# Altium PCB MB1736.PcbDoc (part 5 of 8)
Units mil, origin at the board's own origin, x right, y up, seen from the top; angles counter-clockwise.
Board outline 5905.51 x 3779.53 mil, 6 copper layers (Top Layer, L2_GND, L3_SIG, L4_VCC, L5_GND, Bottom Layer), stack 117.811 mil thick; 481 components, 387 nets, 1904 pads, 1200 vias.
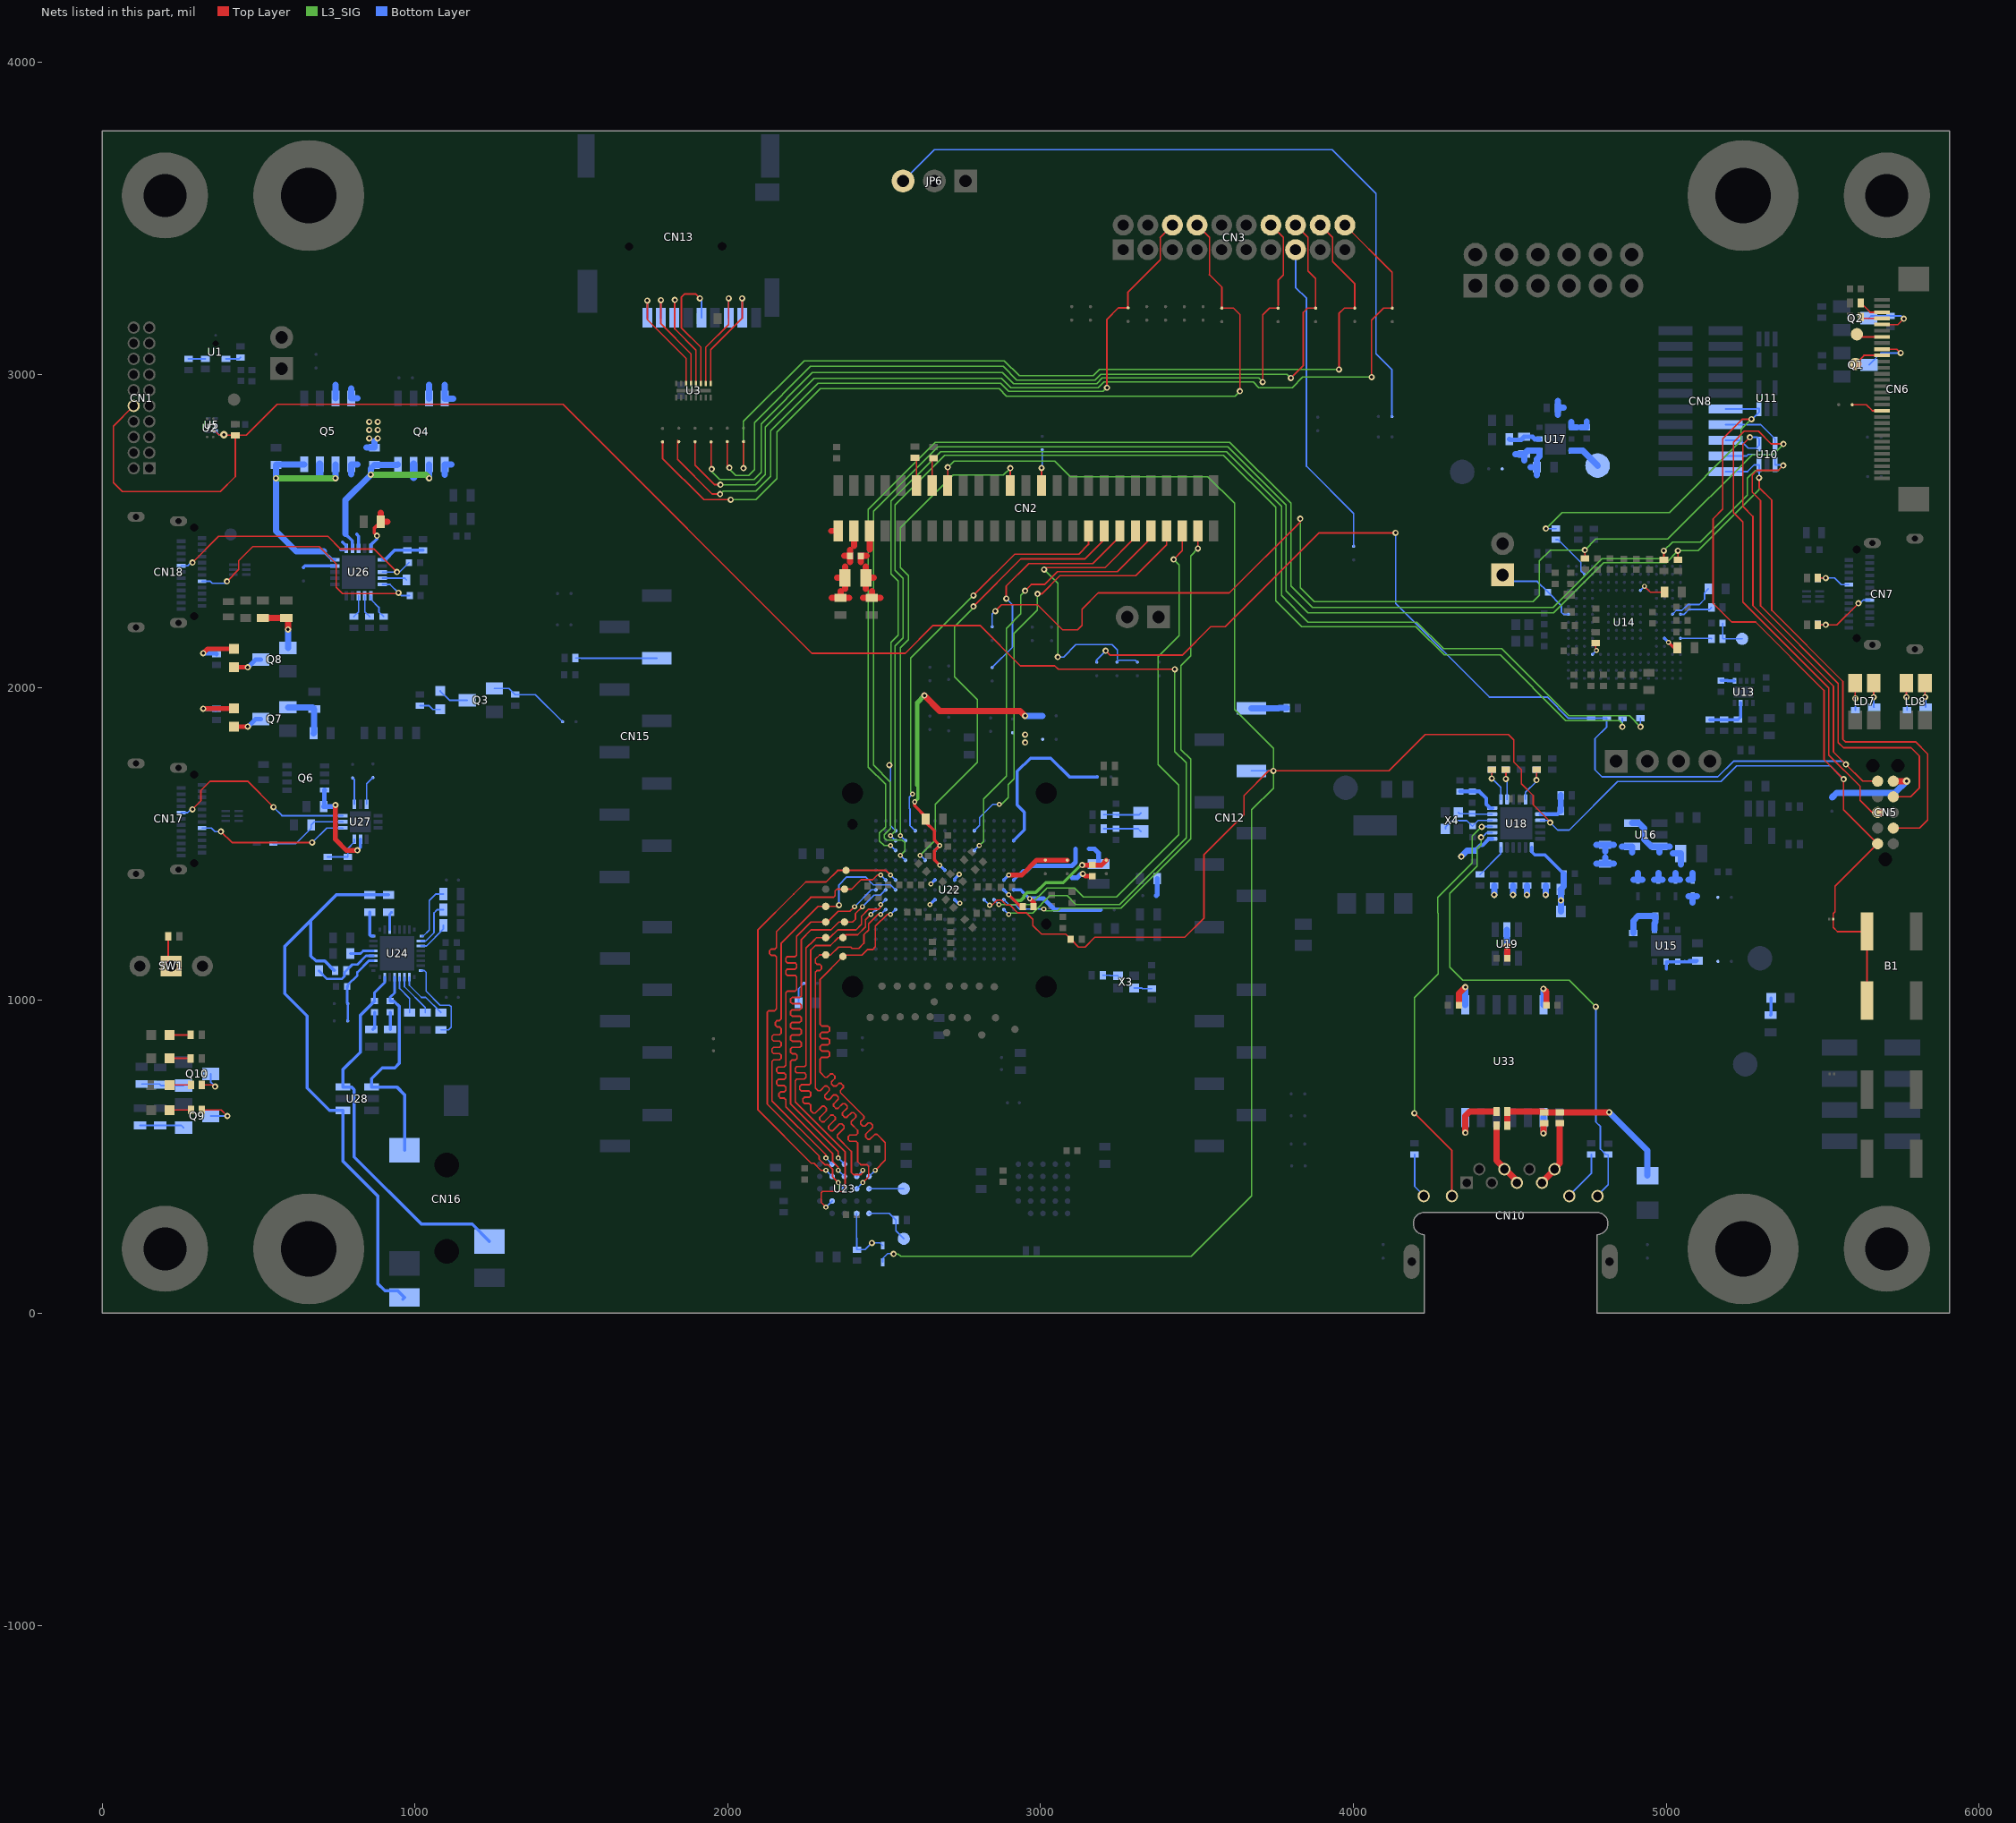
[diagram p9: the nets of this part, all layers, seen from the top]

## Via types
v1: diameter 20, hole 10, Top Layer to Bottom Layer, tented both sides, 518 vias
v2: diameter 16, hole 8, Top Layer to Bottom Layer, tented both sides, 311 vias
v3: diameter 24, hole 10, Top Layer to Bottom Layer, tented both sides, 301 vias
v4: diameter 24, hole 12, Top Layer to Bottom Layer, tented both sides, 61 vias
v5: diameter 23.62, hole 11.81, Top Layer to Bottom Layer, 9 vias

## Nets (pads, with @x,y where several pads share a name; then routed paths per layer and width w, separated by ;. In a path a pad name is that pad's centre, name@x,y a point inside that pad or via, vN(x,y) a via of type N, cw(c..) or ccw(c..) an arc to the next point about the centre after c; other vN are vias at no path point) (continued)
LCD_R0: CN2.3 U22.J2 | length 1725.9
  Top Layer w5: v1(3502.87,2445) 3502.87,2470 CN2.3@3502.88,2501.22
  L3_SIG w4: v2(3010,1292.5) 3015.5,1287 3055.02,1287 3063.02,1295 3257,1295 3479.5,1517.5 3479.5,1771.5 3449,1802 3449,2071 3479.5,2101.5 3479.5,2421.62 v1(3502.87,2445)
  Bottom Layer w5: U22.J2@2882.38,1322.25 2889.8,1314.83 2899.61,1305 2919.99,1305 2932.49,1292.5 v2(3010,1292.5)
LCD_R1: CN2.5 U22.J3 | length 1757.8
  Top Layer w5: v1(3425,2410) 3452.87,2437.86 3452.87,2467 CN2.5@3452.88,2501.22
  L3_SIG w4: v2(2866.61,1306.5) 2867.11,1306 2966.44,1306 3017.44,1357 3018.04,1357 3020.04,1359 3108.01,1359 3136,1331 3242,1331 3441,1530 3441,1688.99 3376,1753.99 3376,2099 3443,2166 3443,2392 v1(3425,2410)
  Bottom Layer w4: U22.J3@2850.87,1322.24 v2(2866.61,1306.5)
LCD_R2: CN2.7 U22.B5 | length 1379.6
  Top Layer w5: v1(2990,2300) 3003.47,2300 3061.48,2358 3304,2358 3402.87,2456.87 3402.87,2471 CN2.7@3402.88,2501.22
  L3_SIG w4: v2(2867.61,1627) 2875.02,1627 2896,1647.98 2896,1689.95 2915,1708.95 2915,2173 2990,2248 v1(2990,2300)
  Bottom Layer w5: U22.B5@2787.9,1542.73 2805,1559.84 2805,1585 2847,1627 v2(2867.61,1627)
LCD_R3: CN2.9 U22.D5 | length 1393.1
  Top Layer w5: v1(2950,2310) 2970,2330 3012.25,2330 3053.26,2371 3245.88,2371 3352.88,2478 CN2.9@3352.88,2501.22
  L3_SIG w4: v2(2803.62,1495.45) 2817,1508.84 2817,1644.92 2890,1717.92 2890,2190 2936.75,2236.75 2936.75,2295.8 v1@2945.95,2305 ; v1@2946,2305 2950,2309 v1(2950,2310)
  Bottom Layer w4: U22.D5@2787.9,1479.74 v2(2803.62,1495.45)
LCD_R4: CN2.11 SB47.1 SB68.1 | length 969.2
  Top Layer w5: v1(3011,2378) 3017,2384 3205.88,2384 3302.88,2481 CN2.11@3302.88,2501.22
  L3_SIG w4: v1(3011,2378) 3055,2334 v1(3055,2098)
  Bottom Layer w4: v1(3055,2098) 3073,2098 3113,2138 3228,2138 3246,2120 3246,2089
  Bottom Layer w5: SB68.1@3244.16,2081.62 3250.48,2087.94 3302.84,2087.94 SB47.1@3309.16,2081.62
LCD_R5: CN2.13 SB53.1 | length 742.1
  Top Layer w5: v1(2890,2285) 2890,2325 2962.01,2397 3167.01,2397 3252.88,2482.88 CN2.13@3252.88,2501.22
  Bottom Layer w5: SB53.1@2845,2064.68 2910,2129.67 2910,2265 v1(2890,2285)
LCD_R6: CN2.15 U22.E10 | length 1483.7
  Top Layer w5: v1(2785,2260) 2937.01,2412 3142.01,2412 3202.87,2472.86 3202.87,2485 CN2.15@3202.88,2501.22
  L3_SIG w4: v2(2614.66,1463.97) 2663.14,1512.44 2663.14,1612.43 2663.76,1613.06 2663.76,1626.76 2798,1761 2798,1962 2725,2035 2725,2195 2785,2255 v1(2785,2260)
  Bottom Layer w4: v2(2614.66,1463.97) 2623.81,1454.82 U22.E10@2630.42,1448.24
LCD_R7: CN2.17 U22.B11 | length 1328
  Top Layer w5: v1(2785,2295) 2917.01,2427 3122.01,2427 3152.87,2457.85 3152.87,2486 CN2.17@3152.88,2501.22
  L3_SIG w4: v2(2590,1660) 2584.87,1665.12 2584.87,2094.86 v1(2785,2295)
  Bottom Layer w5: v2(2590,1660) 2580,1650 2580,1614.53 2582.41,1612.12 2582.41,1559.2 2586.31,1555.31 U22.B11@2598.93,1542.73
LCD_VSYNC: CN2.28 U22.C12 | length 1513.9
  Top Layer w5: CN2.28@2902.88,2646.31 v1(2902.87,2702.12)
  L3_SIG w4: v2(2551.67,1526.95) 2551.67,2127.67 2577,2153 2577,2358.67 2551.67,2384 2551.67,2511.67 2720,2680 2880.74,2680 v1(2902.87,2702.12)
  Bottom Layer w4: v2(2551.67,1526.95) 2559.81,1518.82 U22.C12@2567.43,1511.24
MCU.JTDI: CN5.8 CN8.8 R49.2 SB72.1 U10.5 | length 5134.6
  Top Layer w5: v1(2855,2245) 2875,2265 2990,2265 3070,2185 3118,2185 3132,2199 3132,2251 3184,2303 3603.01,2303 3830,2530 v1(3830,2540) ; R49.2@4740,2412.72 v1(4740,2440) ; v1(5375,2779.36) 5335.63,2779.36 5295,2820 5250,2820 5215,2785 5215,2560 5245,2530 5245,2274 5520,1999 5520,1785 5620,1685 5620,1640 5658.78,1601.22 CN5.8@5676.3,1601.22
  L3_SIG w4: v1(3830,2540) 3830,2320 3875,2275 4575,2275 4595,2295 4595,2405 4630,2440 v1(4740,2440) 4775,2475 5005,2475 5275,2745 5340.63,2745 v1(5375,2779.36)
  Bottom Layer w5: SB72.1@2845,2194.67 2845,2235 v1(2855,2245) ; CN8.8@5190.13,2841 5302.46,2841 5348.35,2795.1 U10.5@5348.35,2779.36 v1(5375,2779.36)
MCU.MCO: C83.2 R78.2 TP4.1 | length 112.3
  Bottom Layer w5: C83.2@5180.59,2206.22 5180.59,2156.22 TP4.1@5242.87,2156.22
MCU.SWCLK: CN5.4 CN8.4 R73.2 U10.1 U22.D13 | length 6577.1
  Top Layer w5: R73.2@4992.76,2408.62 v1(4992.76,2437.75) ; v1(5374.4,2710.6) 5358.79,2695 5290,2695 5275,2680 5275,2625 5301.89,2598.1 5301.89,2261.89 5550,2013.77 5550,1825 5567,1808 5783,1808 5810,1781 5810,1680 5781.22,1651.22 CN5.4@5726.3,1651.22
  L3_SIG w4: v2(2520.17,1495.45) 2499.54,1495.45 2485,1510 2485,1535 2504.16,1554.16 2504.16,1691.23 2449,1746.39 2449,2570.59 2663.41,2785 3605,2785 3800,2590 3800,2325 3869,2256 4639.02,2256 4795.02,2412 4985.02,2412 4992.76,2419.74 v1(4992.76,2437.75) 5020,2465 5110,2465 5260,2615 5260,2670 5285,2695 5358.79,2695 v1(5374.4,2710.6)
  Bottom Layer w4: v2(2520.17,1495.45) 2528.81,1486.82 U22.D13@2535.94,1479.74
  Bottom Layer w5: CN8.4@5190.13,2741 5257.85,2741 5262.76,2745.91 5343.35,2745.91 5348.35,2740.91 U10.1@5348.35,2712.44 5372.57,2712.43 v1(5374.4,2710.6)
MCU.SWDIO: CN5.2 CN8.2 R74.2 U10.3 U22.E12 | length 6470
  Top Layer w5: R74.2@5037.76,2408.62 v1(5037.76,2437.75) ; v1(5297.17,2670.91) 5297.17,2640 5337.5,2599.67 5337.5,2247.5 5565,2020 5565,1835 5573,1827 5797,1827 5836,1788 5836,1577 5810.22,1551.22 CN5.2@5726.3,1551.22
  L3_SIG w4: v2(2551.67,1463.97) 2565.67,1477.97 2565.67,1505 2557.71,1512.95 2507.04,1512.95 2500,1520 2500,1530 2520.16,1550.16 2520.16,1697.85 2465,1753.01 2465,2563.95 2671.04,2770 3598.78,2770 3785,2583.77 3785,2310 3855,2240 4640,2240 4800,2400 5000,2400 v1(5037.76,2437.75) 5102.76,2437.75 5297.17,2632.17 v1(5297.17,2670.91)
  Bottom Layer w4: v2(2551.67,1463.97) 2561.32,1454.32 ; 2561.34,1454.32 U22.E12@2567.43,1448.24
  Bottom Layer w5: CN8.2@5190.13,2691 5260.35,2691 5281.79,2712.43 U10.3@5297.17,2712.44 v1(5297.17,2670.91)
MCU.SWO: CN5.6 CN8.6 R9.1 R51.2 SB31.1 U10.4 | length 4701.4
  Top Layer w5: v1(3208,2118) 3222,2104 3452.78,2104 3543.78,2195 3590.01,2195 3890.01,2495 v1(4135,2495) ; v1(5267.76,2800.91) 5245,2778.15 5245,2580 5277.5,2547.5 5277.5,2262.5 5535,2005 5535,1795 v1(5575,1755) 5628.78,1701.22 CN5.6@5676.3,1701.22
  Bottom Layer w5: SB31.1@3179.16,2081.62 3179.16,2089.16 v1(3208,2118) ; v1(4135,2495) 4135,2270 4435,1970 4620.01,1970 4687.73,1902.27 R51.2@4810,1902.28 4810,1875 4772.5,1837.5 4772.5,1737.5 4795,1715 5165,1715 5215,1765 5565,1765 v1(5575,1755) ; CN8.6@5190.13,2791 5237.68,2791 5262.77,2765.91 5287.75,2765.91 5297.17,2775.33 5297.17,2795.91 5292.17,2800.91 v1(5267.76,2800.91)
MCU.VCP_RX: R56.2 U22.C13 | length 4065.6
  L3_SIG w4: v2(2520.16,1526.97) 2534.16,1540.97 2534.16,2133.16 2560,2159 2560,2350.16 2534.16,2376 2534.16,2584.16 2693,2743 3585,2743 3751.5,2576.5 3751.5,2278.5 3835,2195 4200,2195 4290.66,2104.34 4469.33,2104.34 4678.67,1895 4850,1895 4860,1885 v1(4860,1875)
  Bottom Layer w4: v2(2520.16,1526.97) U22.C13@2535.89,1511.24
  Bottom Layer w5: v1(4860,1875) R56.2@4860,1902.28
MCU.VCP_TX: R52.2 U22.B13 | length 4104.7
  L3_SIG w4: v1(2516.27,1752.85) 2522,1758.59 2522,2145 2545,2168 2545,2341 2522,2364 2522,2597 2680,2755 3595,2755 3770,2580 3770,2295 3855,2210 4201.98,2210 4287.64,2124.34 4474.33,2124.34 4688.67,1910 4882.76,1910 v1(4917.76,1875)
  Bottom Layer w5: v1(2516.27,1752.85) 2516.27,1752.5 2520,1748.77 2520,1558.62 2527.81,1550.82 U22.B13@2535.94,1542.73 ; v1(4917.76,1875) R52.2@4917.76,1903.19
MIC: C137.2 C138.2 CN16.2 R132.1 U28.4 | length 1944.2
  Bottom Layer w10: 666.5,1254.06 666.5,1142.5 683,1126 711,1126 R132.1@741.21,1095.79 ; C137.2@915,1337.56 C138.2@855,1337.56 747.56,1337.56 583,1173 583,1022 655,950 655,720 726.17,648.83 U28.4@769.71,648.83 769.71,485.29 880,375 880,95 903.13,71.87 944.33,71.87 CN16.2@965.77,50.42 CN16.2@960.32,45
MIC_DET: CN1.10 R7.2 U2.6 U5.6 U22.K2 | length 5672.2
  Top Layer w5: CN1.10@100,2901.22 35,2836.22 35,2656 64,2627 377,2627 425,2675 R7.2@425,2807.28 ; U2.6@354.45,2821.02 360.12,2821.02 372.14,2809 v3(389,2809) 390.72,2807.28 407.28,2807.28 ; 407,2807 407.28,2807.28 ; v1(3429.01,2059) 3056,2059 3045,2070 2935,2070 2806,2199 2656,2199 2567,2110 2268.78,2110 1472.56,2906.22 559.22,2906.22 460.28,2807.28 R7.2@425,2807.28 ; 407.28,2807.28 R7.2@425,2807.28
  L3_SIG w4: v2(2898.11,1275) 2903.1,1280 2975,1280 3030,1335 3085.01,1335 3113,1307 3252,1307 3465,1520 3465,1760 3429.01,1796 v1(3429.01,2059)
  Bottom Layer w4: U22.K2@2882.37,1290.75 v2(2898.11,1275)
  Bottom Layer w5: U5.6@361.81,2820.32 373.13,2809 v3(389,2809)
NetC5_2: C5.2 Q6.4 U27.5 | length 327.2
  Top Layer w15: v1(745,1625) 745,1515 780,1480 v1(815,1480)
  Bottom Layer w10: v1(815,1480) 825,1490 825,1508 U27.5@825.02,1515.13
  Bottom Layer w15: Q6.4@710.04,1672.83 710.04,1622.48 C5.2@707.56,1620 740,1620 v1(745,1625)
NetC16_1: C16.1 C18.2 CN2.47 CN2.49 R17.2 | length 393.5
  Top Layer w20: 2330.29,2501.22 CN2.49@2352.88,2501.22 ; 2348.68,2351.22 C16.1@2374.42,2351.22 ; 2360,2308.18 R17.2@2360,2287.57 ; 2372.1,2421.22 C18.2@2390.18,2421.22 ; 2374.42,2315.64 C16.1@2374.42,2351.22 ; 2374.42,2386.8 C16.1@2374.42,2351.22 ; 2402.87,2452.99 2402.87,2477 CN2.47@2402.88,2501.22 ; R17.2@2360,2287.57 2387.71,2287.58 R17.2@2360,2287.57 ; R17.2@2360,2287.57 2332.29,2287.58 R17.2@2360,2287.57 ; C18.2@2390.18,2421.22 2390.17,2440.26 C18.2@2390.18,2421.22 ; C18.2@2390.18,2421.22 2390.17,2402.17 C18.2@2390.18,2421.22
NetC16_2: C16.2 C18.1 CN2.45 R21.2 | length 324.6
  Top Layer w20: 2425.6,2402.17 2425.6,2421.22 2443.66,2421.22 ; 2441.35,2315.64 C16.2@2441.35,2351.22 ; 2441.35,2386.8 C16.2@2441.35,2351.22 ; 2452.87,2442.12 2452.87,2476 CN2.45@2452.88,2501.22 ; 2460,2308.18 R21.2@2460,2287.57 ; 2467.09,2351.22 C16.2@2441.35,2351.22 ; R21.2@2460,2287.57 2487.71,2287.58 R21.2@2460,2287.57 ; R21.2@2460,2287.57 2432.29,2287.58 R21.2@2460,2287.57
NetC27_2: C27.2 SB35.2 U22.D9 U22.F8 | length 1055.1
  Top Layer w10: v2(2597.5,1635) 2597.5,1622.5 2632.44,1587.56 2632.44,1570.08 2660.03,1542.49 2660.03,1513.09 v2(2677.63,1495.5) 2660.03,1477.9 2660.03,1450.09 v2(2677.65,1432.47)
  Top Layer w20: v1(2628.37,1975) 2677.36,1926 2934,1926 v1(2950,1910)
  L3_SIG w10: v2(2597.5,1635) 2608,1645.5 2608,1687 2605.5,1689.5
  L3_SIG w15: 2605.5,1689.5 2605,1690 2605,1951.62 v1(2628.37,1975)
  Bottom Layer w10: U22.D9@2661.92,1479.74 2667.76,1485.59 v2(2677.63,1495.5) ; v2(2677.65,1432.47) 2686.06,1424.06 U22.F8@2693.4,1416.74
  Bottom Layer w20: v1(2950,1910) SB35.2@3006.38,1910
NetC43_1: C43.1 C44.1 SB28.2 U22.H2 | length 458.4
  Top Layer w10: v2(2898.06,1338.07) 2936.13,1300 C43.1@2942.3,1300
  Top Layer w15: v1(3132.72,1432.72) 3194.09,1432.72 SB28.2@3210,1448.62
  L3_SIG w10: v2(2898.06,1338.07) 2898.06,1336.93 2915,1320 2930,1320 2930.19,1320.18 2937.03,1320.18 2947.03,1330.18 2947.03,1335 2957.03,1345 2984.22,1345 3016.22,1377 3072.41,1377 3128.13,1432.72 v1(3132.72,1432.72)
  Bottom Layer w10: U22.H2@2882.39,1353.76 v2(2898.06,1338.07)
NetC43_2: C43.2 SB55.2 U22.H1 | length 335.7
  Top Layer w15: v2(2965.03,1325.81) 2977.72,1313.11 C43.2@2977.73,1300
  Bottom Layer w10: U22.H1@2913.89,1353.76 2914.31,1354.18 2935.86,1354.18 2945.81,1344.24 2945.81,1344.17 2954.65,1335.26 2963.96,1325.89 2964.97,1325.86 v2(2965.03,1325.81)
  Bottom Layer w15: v2(2965.03,1325.81) 3009.19,1325.81 3045,1290 SB55.2@3191.69,1290
NetC44_2: C44.2 SB36.1 | length 73.5
  Top Layer w15: v1(3135,1405) 3142.73,1397.27 C44.2@3165,1397.28
  Bottom Layer w15: SB36.1@3100,1392.28 3116.27,1392.27 3129,1405 v1(3135,1405)
NetC49_2: C49.2 C91.2 C92.2 C98.2 C100.2 C102.1 L1.1 R95.2 R98.2 R100.2 R103.2 U18.1 U18.19 U19.5 U33.2 U33.7 | length 833.6
  Top Layer w20: C92.2@4337.72,985 4337.72,1022.72 v1(4357.76,1042.75) ; v1(4490.76,1175) 4492.72,1173.03 C49.2@4492.74,1135 ; v1(4607.76,1037.24) 4617.28,1027.72 C91.2@4617.29,985
  Bottom Layer w10: U18.19@4569.99,1489.34 4569.98,1475 4579.99,1465 4612.28,1465 C100.2@4672.29,1405
  Bottom Layer w12: C98.2@4385.75,1478.83 4386.74,1478.84 4404.56,1496.66 4412.92,1496.66 4433.17,1516.91 U18.1@4444,1516.9
  Bottom Layer w20: v1(4345,1460) 4363.84,1478.84 C98.2@4385.75,1478.83 ; U33.2@4357.76,986.02 v1(4357.76,1042.75) ; v1(4450,1337.59) R103.2@4450,1367.3 ; v1(4490.76,1175) U19.5@4490.78,1226.01 ; v1(4510,1337.59) R100.2@4510,1367.3 ; v1(4555,1337.59) R98.2@4555,1367.3 ; U33.7@4607.76,986.02 v1(4607.76,1037.24) ; v1(4615,1337.59) R95.2@4615,1367.3 ; L1.1@4663.5,1285 v1(4663.5,1320) 4663.5,1353.93 C102.1@4662.44,1355 4672.28,1364.84 C100.2@4672.29,1405
NetC69_2: C69.2 U14.M10 | length 91
  Top Layer w5: v2(4930.58,2324.17) 4949.76,2305 4985.81,2305 4986.72,2305.91 C69.2@4995.2,2305.91
  Bottom Layer w4: U14.M10@4917.8,2311.4 v2(4930.58,2324.17)
NetC70_2: C70.2 U14.F13 | length 53.6
  Top Layer w10: v2(5007.35,2145.03) 5024.88,2127.51 C70.2@5035.56,2127.51
  Bottom Layer w10: U14.F13@4994.59,2157.85 v2(5007.35,2145.03)
NetC82_1: C82.1 U14.J14 | length 161.2
  Bottom Layer w5: U14.J14@5020.18,2234.63 5032.92,2247.38 5050.78,2247.38 5069.1,2265.69 5105.7,2265.69 5123.01,2283 5123.01,2303.92 C82.1@5135.32,2316.22
NetC84_2: C84.2 U13.1 | length 43.8
  Bottom Layer w10: C84.2@5175,2022.72 5196.03,2022.72 5196.66,2022.09 U13.1@5218.53,2022.1
NetC85_2: C85.2 D3.2 D4.2 D5.2 D6.2 U16.3 U16.5 | length 433.7
  Bottom Layer w20: U16.5@4891.7,1567.4 4912.6,1567.4 4930,1550 4930,1514.99 4952.39,1492.59 U16.3@4978.32,1492.6 ; 4896.07,1386.57 D6.2@4910,1386.56 ; 4910,1407.39 D6.2@4910,1386.56 ; 4923.93,1386.57 D6.2@4910,1386.56 ; 4961.07,1386.57 D5.2@4975,1386.56 ; 4975,1407.39 D5.2@4975,1386.56 ; 4978.31,1472.76 U16.3@4978.32,1492.6 ; 4988.93,1386.57 D5.2@4975,1386.56 ; 5011.92,1492.59 U16.3@4978.32,1492.6 ; 5016.07,1386.57 D4.2@5030,1386.56 ; 5020.79,1470 C85.2@5046.53,1470 5046.53,1434.42 ; 5030,1407.39 D4.2@5030,1386.56 ; 5043.93,1386.57 D4.2@5030,1386.56 ; 5071.07,1386.57 D3.2@5085,1386.56 5085,1407.39
NetC86_2: C86.2 SB21.1 U15.4 U15.5 | length 158.5
  Bottom Layer w10: 5000.02,1100.01 U15.5@5000.02,1123.83 5058.84,1123.84 ; 5060,1125 5058.84,1123.84 ; 5058.84,1123.84 5070,1123.84 ; 5070,1123.84 5073.63,1127.45 5100,1127.45 5096.38,1123.84 5070,1123.84
NetC89_2: C89.2 R82.2 U15.1 | length 160.7
  Bottom Layer w20: R82.2@4895,1215.74 4895,1255 4910,1270 C89.2@4965.32,1270 4965.31,1250.31 4962.62,1247.61 U15.1@4962.62,1226.2
NetC90_2: C90.2 R91.2 U17.1 | length 211.9
  Bottom Layer w20: 4671.81,2894.77 R91.2@4653.76,2894.77 ; 4726.97,2832.5 C90.2@4746.02,2832.51 4746.02,2850.57 ; R91.2@4653.76,2894.77 4653.76,2916.58 R91.2@4653.76,2894.77 ; R91.2@4653.76,2894.77 4653.76,2872.98 R91.2@4653.76,2894.77 ; U17.1@4697.23,2832.2 4715.08,2832.19 U17.1@4697.23,2832.2 ; U17.1@4697.23,2832.2 4697.22,2849.08 U17.1@4697.23,2832.2
NetC93_2: C93.2 R97.2 SB23.1 U17.4 | length 203.2
  Bottom Layer w20: 4518.31,2747.23 R97.2@4546.02,2747.24 ; 4546.02,2726.6 R97.2@4546.02,2747.24 ; 4565.8,2705.22 C93.2@4586.42,2705.22 ; 4586.42,2679.67 C93.2@4586.42,2705.22 ; R97.2@4546.02,2747.24 4556.18,2757.39 U17.4@4594.86,2757.39 4594.85,2739.18 4586.42,2730.75 C93.2@4586.42,2705.22
NetC94_2: C94.2 JP3.1 U14.J1 | length 274.9
  Bottom Layer w5: JP3.1@4477.07,2360.5 4497.57,2340 4587.72,2340 C94.2@4622.73,2305 4665,2262.72 4665,2241.73 4672.11,2234.61 U14.J1@4687.5,2234.63
NetC99_2: C99.2 C101.2 U18.6 | length 136.3
  Bottom Layer w12: C101.2@4340.75,1668.4 4402.78,1668.4 4425,1646.17 4425,1627.33 4437,1615.33 U18.6@4444,1615.33
NetC106_2: C106.2 SB29.1 | length 56.2
  Bottom Layer w15: SB29.1@3369.69,1335 3372.56,1337.88 C106.2@3372.56,1390
NetC108_2: C108.2 R111.1 X2.1 | length 122.9
  Bottom Layer w5: R111.1@3201.73,1549.26 C108.2@3240.87,1549.27 3312.03,1549.25 X2.1@3320.88,1540.42
NetC109_2: C109.2 R112.1 X2.2 | length 121.6
  Bottom Layer w5: R112.1@3201.73,1593.93 3240.76,1593.93 C109.2@3240.87,1593.84 3315.24,1593.83 X2.2@3320.88,1599.47
NetC114_2: C114.2 SB40.1 | length 69
  Bottom Layer w5: C114.2@2226,993 2226,1038 SB40.1@2243,1055
NetC129_2: C129.2 SB52.2 SB54.2 U24.19 | length 237.1
  Bottom Layer w8: C129.2@782.72,1045 782.72,991.65 SB54.2@784.53,989.84 SB52.2@784.53,934.84 ; C129.2@784.53,1043.19 784.53,1049.53 815,1080 815,1090 852.17,1127.17 U24.19@866.34,1127.17
NetC130_1: C130.1 U24.11 | length 141
  Bottom Layer w5: U24.11@965.75,1075 965.75,1044.25 1032.13,977.87 C130.1@1032.13,961.5
NetC131_1: C131.1 U24.12 | length 126.8
  Bottom Layer w5: U24.12@950,1075 950,1038.66 982.13,1006.54 C131.1@982.13,961.5
NetC132_1: C132.1 U24.10 | length 163.2
  Bottom Layer w5: U24.10@981.5,1075 981.5,1048.5 1020,1010 1033.62,1010 C132.1@1082.13,961.5
NetC132_2: C132.2 U24.8 | length 281.6
  Bottom Layer w5: U24.8@1017.91,1095.67 1029.33,1095.67 1035,1090 1035,1030 1080,985 1110,985 1115,980 1115,915 1106.38,906.38 C132.2@1082.13,906.38
NetC133_1: C133.1 R132.2 U24.20 | length 222.2
  Bottom Layer w8: C133.1@692.56,1095 718.56,1069 765,1069 773.8,1077.8 773.8,1089.75 799.06,1115 815,1115 842.91,1142.91 U24.20@866.34,1142.91
NetC134_2: C134.2 U24.21 | length 77.4
  Bottom Layer w8: C134.2@792.56,1150 825,1150 833.66,1158.66 U24.21@866.34,1158.66
NetC137_1: C137.1 U24.27 | length 58.6
  Bottom Layer w8: U24.27@918.5,1226.57 918.5,1275.94 C137.1@925,1282.44
NetC138_1: C138.1 U24.24 | length 85.5
  Bottom Layer w10: C138.1@855,1282.44 855,1210 859.09,1205.91 U24.24@866.34,1205.91
NetC140_1: C140.1 CN16.4 U24.15 U28.6 | length 1204.8
  Bottom Layer w8: C140.1@870,997.72 870,1025 902.76,1057.76 U24.15@902.76,1075
  Bottom Layer w10: C140.1@870,997.72 825,952.72 825,835 769.71,779.71 U28.6@769.71,723.64 796.36,723.64 805,715 805,500 1020,285 1181.98,285 CN16.4@1237.42,229.56
NetC140_2: C140.2 R145.2 | length 56.8
  Bottom Layer w10: R145.2@865,907.56 870,912.56 C140.2@870,962.28
NetC141_1: C141.1 CN16.6 U24.13 U28.1 | length 731.4
  Bottom Layer w8: C141.1@920,997.72 920,1010.4 934.25,1024.65 U24.13@934.25,1075
  Bottom Layer w10: C141.1@920,997.72 932.28,997.72 950,980 950,800 935,785 895,785 860.26,750.26 U28.1@860.26,723.64 941.36,723.64 965.77,699.23 CN16.6@965.77,520.9
NetC141_2: C141.2 R146.2 | length 54.7
  Bottom Layer w10: R146.2@920,907.56 C141.2@920,962.28
NetC145_1: C145.1 U26.14 | length 79.8
  Bottom Layer w5: U26.14@894.93,2350.04 967.02,2350.02 C145.1@972.44,2344.6
NetC146_2: C146.2 CN18.A5 U26.15 | length 904.6
  Top Layer w5: v1(398,2340) 436,2378 436,2406 480.91,2450.91 692.76,2450.91 747.76,2395.91 747.76,2320.91 767.76,2300.91 943.91,2300.91 v1(946.5,2303.5)
  Bottom Layer w5: CN18.A5@318.75,2340.47 344.52,2340.48 351,2334 392.01,2334 v1(398,2340) ; U26.15@894.93,2330.35 919.65,2330.34 v1(946.5,2303.5) 955.39,2294.6 C146.2@982.3,2294.6
NetC147_2: C147.2 CN18.B5 U26.13 | length 874.1
  Top Layer w5: v1(287.76,2400) 371.76,2484 721,2484 762,2443 868.71,2443 v1(942,2369.7)
  Bottom Layer w5: CN18.B5@251.82,2389.68 272.45,2389.68 282.76,2400 v1(287.76,2400) ; U26.13@894.93,2369.73 921.99,2369.72 v1(942,2369.7) 950.1,2369.7 C147.2@980,2399.6
NetC150_1: C150.1 Q4.7 Q4.8 Q5.7 Q5.8 R134.1 U26.10 | length 411.9
  Top Layer w10: v1(877.76,2485.91) 868.62,2495.05 868.62,2509.2 R134.1@890.32,2530.91
  Top Layer w20: 890.32,2558.61 R134.1@890.32,2530.91 910.94,2530.91
  Bottom Layer w10: U26.10@858.52,2445.51 858.51,2456.67 877.76,2475.92 v1(877.76,2485.91)
  Bottom Layer w20: Q5.7@745,2924.92 745,2968.67 ; 795,2957.56 Q5.8@795,2924.92 815.82,2924.92 ; 844.46,2767.57 C150.1@870,2767.57 870,2788.18 ; Q4.7@1045,2924.6 1045,2968.15 ; 1095,2968.67 Q4.8@1095,2924.6 1121.46,2924.6
  other v1: 853,2797 880,2797 853,2824 880,2824 853,2850 880,2850
NetC150_2: C150.2 Q4.2 Q4.4 U26.7 | length 626
  L3_SIG w20: v1(857.91,2680.91) 1034.09,2680.91 v1(1045,2670)
  Bottom Layer w10: 777,2491.67 799.44,2469.23 U26.7@799.46,2445.51
  Bottom Layer w20: 777,2491.67 777,2600 v1(857.91,2680.91) 857.91,2700.36 870,2712.45 943.48,2712.45 Q4.4@945,2713.98 ; v1(1045,2670) Q4.2@1045,2713.98
NetC153_1: C153.1 D7.2 U27.8 | length 257.5
  Bottom Layer w5: D7.2@546.59,1501.22 618.06,1501.22 667.56,1550.72 C153.1@667.56,1561.22 677.56,1571.22 U27.8@768.9,1571.22
NetC157_2: C157.2 Q5.2 Q5.4 U26.5 | length 763.5
  L3_SIG w20: v1(555,2670) v1(745,2670)
  Bottom Layer w10: 707.76,2435.91 734.57,2409.09 U26.5@743.36,2409.1
  Bottom Layer w20: Q5.4@645,2714.3 556.84,2714.3 555,2712.45 v1(555,2670) 555,2499.99 619.08,2435.91 707.76,2435.91 ; v1(745,2670) Q5.2@745,2714.3
NetC158_2: C158.2 R172.1 R173.1 R174.1 R175.1 | length 624.2
  Top Layer w20: R173.1@4492.72,600 R172.1@4492.72,645 4607.72,645 R175.1@4610,642.71 v1(4817.72,642.72)
  Bottom Layer w20: v1(4817.72,642.72) 4940,520.43 C158.2@4940,440.11
NetC159_2: C159.2 U18.4 X4.1 | length 178.8
  Bottom Layer w5: X4.1@4294.33,1548.42 4294.33,1554.33 4315,1575 4362.72,1575 4380,1557.72 C159.2@4380.99,1557.72 4399.23,1575.95 U18.4@4444,1575.95
NetC160_2: C160.2 U18.5 X4.3 | length 110.8
  Bottom Layer w5: X4.3@4335.67,1601.56 4339.96,1597.27 4388.53,1597.27 4390.16,1595.65 U18.5@4444,1595.64
NetCN2_24: CN2.24 SB34.1 | length 114.9
  Top Layer w5: CN2.24@3002.88,2646.31 3002.88,2667.99 v1(3002.87,2702.86)
  Bottom Layer w5: v1(3002.87,2702.86) 3005,2705 SB34.1@3005,2760.33
NetCN2_38: CN2.38 R32.1 | length 89.3
  Top Layer w5: CN2.38@2652.88,2646.31 2652.88,2651.99 2652.87,2728.5 R32.1@2657.87,2733.52
NetCN2_40: CN2.40 R29.1 | length 91.6
  Top Layer w5: R29.1@2597.87,2735.8 2602.87,2730.77 CN2.40@2602.88,2646.31
NetCN3_8: CN3.8 SB51.2 | length 1025.2
  Bottom Layer w5: CN3.8@3815.22,3400.25 3815.22,3279.77 3850,3245 3850,2708 4001,2557 SB51.2@4001,2452
NetCN3_13: CN3.13 SB3.1 SB4.1 | length 2352.7
  Top Layer w4: 3382.15,3368.15 3382.15,3439.62
  Top Layer w5: 1839,2791 1839,2730 1950,2619 v1(1975,2619) ; v1(3212,2959) 3212,3178 3248.43,3214.43 SB4.1@3279.31,3214.43 3279.31,3265.31 3382.15,3368.15 ; 3382.15,3439.62 CN3.13@3421.52,3479
  L3_SIG w4: v1(1975,2619) 1985,2629 2090,2629 2137,2676 2137,2822 2288,2973 2872,2973 2898,2947 3200,2947 v1(3212,2959)
NetCN3_14: CN3.14 SB9.1 SB10.1 | length 2813.8
  Top Layer w4: 3539.63,3320.37 3539.63,3439.62
  Top Layer w5: SB10.1@1791,2785.69 1791,2733 1923,2601 v1(2009,2601) ; CN3.14@3500.26,3479 3539.63,3439.62 ; 3539.63,3320.37 3579.31,3280.69 SB9.1@3579.31,3213.37 3616.66,3213.34 3637,3193 v1(3637,2948)
  L3_SIG w4: v1(2009,2601) 2089,2601 2157,2669 2157,2818 2295,2956 2867,2956 2891,2932 3621,2932 v1(3637,2948)
NetCN3_17: CN3.17 SB11.1 SB12.1 | length 2691.7
  Top Layer w4: SB11.1@1946,2785.69 1946,2694 1948,2696 v1(1948,2699) ; 3775.85,3319.84 3775.85,3439.62
  Top Layer w5: v1(3710,2977) 3710,3192 3731.37,3213.37 SB12.1@3759.31,3213.37 SB12.1@3757.93,3211.97 ; CN3.17@3736.48,3479 3775.85,3439.62 ; 3760,3222 3760,3304 3775.85,3319.84
  L3_SIG w4: v1(1948,2699) 1948,2692 1974,2666 2084,2666 2106,2688 2106,2843 2270,3007 2878,3007 2913,2972 3179,2972 3197,2990 3697,2990 v1(3710,2977)
NetCN3_18: CN3.18 SB13.1 SB14.1 | length 2720.3
  Top Layer w4: SB13.1@1998,2786.69 1998,2710 v1(2005,2703) ; 3854.59,3332.41 3854.59,3439.62
  Top Layer w5: v1(3800,2990) 3840,3030 3840,3200 3853.34,3213.34 3879.31,3213.34 3879.31,3307.69 3854.59,3332.41 ; CN3.18@3815.22,3479 3854.59,3439.62
  L3_SIG w4: v1(2005,2703) 2005,2699 2025,2679 2067,2679 2085,2697 2085,2848 2264,3027 2881,3027 2924,2984 3174,2984 3192,3002 3788,3002 v1(3800,2990)
NetCN3_19: CN3.19 SB15.1 SB16.1 | length 2794.5
  Top Layer w4: v1(2050,2702) SB15.1@2050,2786.69 ; 3933.33,3362.67 3933.33,3439.62
  Top Layer w5: CN3.19@3893.96,3479 3933.33,3439.62 ; 3933.33,3362.67 4003.99,3292.01 SB16.1@4003.99,3213.34 ; v1(3954,3017) 3954,3196 3971.34,3213.34 SB16.1@4003.99,3213.34 ; SB16.1@4003.99,3213.34 SB16.1@4004.31,3213.68 SB16.1@4004,3213.34
  L3_SIG w4: v1(2050,2702) 2050,2851 2244,3045 2884,3045 2932,2997 3168,2997 3188,3017 v1(3954,3017)
NetCN3_20: CN3.20 SB17.1 SB18.1 | length 3128.3
  Top Layer w5: SB17.1@1895,2786.32 1895,2712 1958,2649 v1(1976,2649) ; CN3.20@3972.7,3479 4124,3327.69 4124,3213.67 4124.3,3213.37 4096.37,3213.37 4058,3175 v1(4058,2993)
  L3_SIG w4: v1(1976,2649) 2088,2649 2120,2681 2120,2833 2276,2989 2875,2989 2905,2959 3184,2959 3202,2977 3680,2977 3698,2959 3804,2959 3838,2993 v1(4058,2993) v1@4059,2993
NetCN5_5: CN5.5 SB71.2 | length 303
  Top Layer w20: CN5.5@5726.3,1701.22 v3(5768.78,1701.22)
  Bottom Layer w20: SB71.2@5530,1648.62 5544.99,1663.61 5731.18,1663.61 v3(5768.78,1701.22)
NetCN6_12: CN6.12 SB19.1 | length 103.1
  Top Layer w5: SB19.1@5595.02,2905 5640,2905 5659.64,2885.35 CN6.12@5690,2885.35
NetCN6_21: CN6.21 TP1.1 | length 96.4
  Top Layer w5: TP1.1@5605,3035 5632.52,3062.51 CN6.21@5690,3062.51
NetCN6_22: CN6.22 Q1.3 | length 181.9
  Top Layer w5: CN6.22@5690,3082.2 5737.79,3082.2 v1(5750,3070)
  Bottom Layer w5: Q1.3@5648.8,3032.22 5686.58,3070 v1(5750,3070)
NetCN6_24: CN6.24 TP2.1 | length 83.5
  Top Layer w5: TP2.1@5610,3130 5618.42,3121.58 CN6.24@5690,3121.58
NetCN6_26: CN6.26 Q2.3 R61.1 | length 196.4
  Top Layer w5: CN6.26@5690,3160.94 5740.95,3160.94 v1(5760,3180)
  Bottom Layer w5: Q2.3@5647.98,3181.19 5655.23,3188.44 R61.1@5717,3188.45 5751.55,3188.44 v1(5760,3180)
NetCN6_27: CN6.27 R57.1 | length 69.1
  Top Layer w5: R57.1@5622.74,3185 5627.1,3180.62 CN6.27@5690,3180.62
NetCN6_28: CN6.28 R58.1 | length 79.6
  Top Layer w5: R58.1@5622.74,3230 5652.41,3200.32 CN6.28@5690,3200.32
NetCN7_A5: CN7.A5 R53.2 R72.1 | length 132.5
  Top Layer w5: R53.2@5485.48,2350.91 v1(5510.52,2350.91)
  Bottom Layer w5: R72.1@5485.48,2350.9 v1(5510.52,2350.91) 5539.09,2350.91 5560.47,2329.52 CN7.A5@5584.02,2329.52
NetCN7_B5: CN7.B5 R54.2 R71.1 | length 223.4
  Top Layer w5: R54.2@5485.48,2200.91 v1(5510.52,2200.91) 5545.92,2200.91 v1(5615.01,2270)
  Bottom Layer w5: R71.1@5485.48,2200.9 v1(5510.52,2200.91) ; v1(5615.01,2270) 5620.01,2270 5630.33,2280.32 CN7.B5@5650.93,2280.3
NetCN10_4: CN10.4 CN10.5 R173.2 | length 207.5
  Top Layer w20: R173.2@4457.29,600 4457.28,488.4 4522.84,422.84 CN10.5@4522.84,419.69
NetCN10_7: CN10.7 CN10.8 R174.2 | length 211.1
  Top Layer w20: CN10.7@4603.15,419.69 4643.31,459.84 4643.31,463 4660,479.68 R174.2@4660,607.28
NetCN10_9: CN10.9 R107.2 | length 142.9
  Bottom Layer w5: R107.2@4195.76,508.01 4195.76,406.22 CN10.9@4224.81,377.16
NetCN10_10: CN10.10 U18.3 | length 1351.6
  Top Layer w5: v1(4195,640) 4314.96,520.03 CN10.10@4314.96,377.16
  L3_SIG w4: v1(4195,640) 4195,1009.4 4270.6,1085 4270.6,1279.4 4270,1280 4270,1330 4380,1440 4380,1525 v1(4410,1555)
  Bottom Layer w5: v1(4410,1555) 4411.26,1556.25 U18.3@4443.98,1556.25
NetCN10_11: CN10.11 R87.2 | length 159.9
  Bottom Layer w5: CN10.11@4690.55,377.16 4760.76,447.38 R87.2@4760.76,508.01
NetCN10_12: CN10.12 R85.2 U18.2 | length 1655.6
  L3_SIG w4: v1(4408.28,1521.73) 4408.28,1498.26 4395,1484.99 4395,1430 4308,1343 4308,1107 4350,1065 4690,1065 v1(4775,980)
  Bottom Layer w5: v1(4408.28,1521.73) 4411.82,1521.73 4426.68,1536.59 U18.2@4444,1536.59 ; v1(4775,980) 4775,612 4790,597 4790,525 4807.7,507.3 R85.2@4815,507.3 4815,411.45 CN10.12@4780.71,377.16
NetCN12_1: CN12.1 R108.1 | length 113.6
  Bottom Layer w20: CN12.1@3674,1934.25 3761.51,1934.25 3762.25,1935 R108.1@3787.3,1935
NetCN13_1: CN13.1 U3.14 | length 371.3
  Top Layer w5: v1(1742.4,3237.4) 1742.4,3176.6 1866.38,3052.62 U3.14@1866.38,2972.63
  Bottom Layer w5: CN13.1@1742.41,3182.22 1742.41,3203.99 v1(1742.4,3237.4)
NetCN13_2: CN13.2 U3.13 | length 363.7
  Top Layer w5: v1(1785.71,3239.28) 1785.71,3163.29 1882.13,3066.87 U3.13@1882.13,2972.63
  Bottom Layer w5: CN13.2@1785.71,3182.22 1785.72,3200.99 v1(1785.71,3239.28)
NetCN13_3: CN13.3 U3.12 | length 353.7
  Top Layer w5: v1(1830,3240) 1830,3147 1897.87,3079.13 U3.12@1897.87,2972.63
  Bottom Layer w5: CN13.3@1829.02,3182.22 1829.02,3208.99 1829.01,3239 v1(1830,3240)
NetCN13_5: CN13.5 U3.11 | length 435.8
  Top Layer w5: v1(1910,3245) 1896,3259 1862,3259 1851,3248 1851,3151 1913.62,3088.38 U3.11@1913.62,2972.63
  Bottom Layer w5: v1(1910,3245) 1915.63,3239.36 CN13.5@1915.64,3182.22
NetCN13_7: CN13.7 U3.10 | length 365.4
  Top Layer w5: U3.10@1929.37,2972.63 1929.37,3088.37 2002.24,3161.24 v1(2002.24,3245)
  Bottom Layer w5: CN13.7@2002.25,3182.22 v1(2002.24,3245)
NetCN13_8: CN13.8 U3.9 | length 375.7
  Top Layer w5: U3.9@1945.12,2972.63 1945.12,3080.12 2045.55,3180.55 v1(2045.55,3244.44)
  Bottom Layer w5: CN13.8@2045.56,3182.22 v1(2045.55,3244.44)
NetCN15_8: CN15.8 R120.1 | length 260
  Bottom Layer w5: R120.1@1512.74,2095 1530.26,2095 1531.01,2094.25 CN15.8@1772.37,2094.25
NetCN17_A5: CN17.A5 U27.7 | length 488.7
  Top Layer w5: v1(379,1540) 414,1505 v1(671,1505)
  Bottom Layer w5: CN17.A5@318.75,1551.46 348.53,1551.47 360,1540 v1(379,1540) ; v1(671,1505) 717.54,1551.53 U27.7@768.92,1551.55
NetCN17_B5: CN17.B5 U27.9 | length 623.5
  Top Layer w5: v1(287.76,1610.99) 315,1638.23 315,1671 345,1701 464,1701 v1(547,1618)
  Bottom Layer w5: CN17.B5@251.82,1600.67 272.45,1600.67 282.76,1610.99 v1(287.76,1610.99) ; v1(547,1618) 574.1,1590.9 U27.9@768.9,1590.9
NetD1_1: D1.1 R117.1 U23.A4 | length 210.9
  Bottom Layer w4: 2411.89,240.9 U23.A4@2411.89,319.44
  Bottom Layer w5: 2411.89,240.9 2411.89,204.27 R117.1@2412.52,203.64 2438.64,203.64 v1(2460,224.99) 2486.57,224.99 D1.1@2494.99,216.57
NetD3_1: D3.1 SB22.1 | length 48.7
  Bottom Layer w20: 5071.07,1333.42 D3.1@5085,1333.42 ; 5085,1312.59 D3.1@5085,1333.42 ; 5098.93,1333.42 D3.1@5085,1333.42
NetJP6_3: JP6.3 SB50.1 | length 2345.7
  Bottom Layer w5: JP6.3@2560,3620 2660.01,3720 3932,3720 4072,3580 4072,3068 4123.31,3016.69 SB50.1@4123.31,2867
NetL4_2: L4.2 SB44.1 | length 71.3
  Bottom Layer w15: SB44.1@3154.69,1485 3172.18,1485 3185,1472.17 L4.2@3185,1436.49
NetLD1_2: LD1.2 R5.2 | length 67.8
  Top Layer w5: LD1.2@215.02,650 R5.2@282.78,650
NetLD2_2: LD2.2 R6.2 | length 67.8
  Top Layer w5: LD2.2@215.02,730 R6.2@282.78,730
NetLD3_2: LD3.2 R3.2 | length 67.8
  Top Layer w5: LD3.2@214.55,815 R3.2@282.3,815
NetLD4_2: LD4.2 R4.2 | length 67.8
  Top Layer w5: LD4.2@214.55,890 R4.2@282.3,890
NetLD5_1: LD5.1 R166.2 | length 155.5
  Top Layer w15: v1(322,1933) LD5.1@420,1933 ; LD5.1@420,1934.53 LD5.1@420,1933 ; LD5.1@425.48,1930 422.48,1933 LD5.1@420,1933
  Bottom Layer w15: v1(322,1933) 359.29,1933 R166.2@362.29,1930 ; R166.2@362.29,1930 R166.2@365,1932.72 R166.2@362.29,1930
NetLD5_2: LD5.2 Q7.3 | length 96.9
  Top Layer w15: LD5.2@420,1875.48 430,1875.47 v1(464.93,1875.47)
  Bottom Layer w15: v1(464.93,1875.47) 465.75,1875.47 490.28,1900 Q7.3@506.69,1900
NetLD6_1: LD6.1 R167.2 | length 156.2
  Top Layer w15: v1(322,2110) 336.54,2124.53 LD6.1@420,2124.53 ; LD6.1@411.81,2124.52 LD6.1@420,2124.53
  Bottom Layer w15: v1(322,2110) 362.72,2110 R167.2@365,2107.72
NetLD6_2: LD6.2 Q8.3 | length 97.3
  Top Layer w15: LD6.2@420,2065.48 430,2065.47 464.53,2065.47 v1(465,2065)
  Bottom Layer w15: v1(465,2065) 490,2090 Q8.3@506.69,2090
NetLD7_1: LD7.1 R63.1 | length 87.6
  Top Layer w5: v1(5604.47,1965) LD7.1@5604.48,2015.05
  Bottom Layer w5: v1(5604.47,1965) 5605,1964.47 R63.1@5605,1927.72
NetLD7_2: LD7.2 R62.1 | length 78.1
  Top Layer w5: v1(5663.53,1970) LD7.2@5663.54,2015.05
  Bottom Layer w5: v1(5663.53,1970) 5663.53,1939.02 R62.1@5665,1937.56
NetLD8_1: LD8.1 R60.1 | length 88
  Top Layer w5: v1(5768.47,1970) LD8.1@5768.49,2015.05
  Bottom Layer w5: v1(5768.47,1970) 5770,1968.47 R60.1@5770,1927.72
NetLD8_2: LD8.2 R59.1 | length 78.5
  Top Layer w5: LD8.2@5827.54,2015.05 5827.53,1970.47 v1(5828,1970)
  Bottom Layer w5: v1(5828,1970) 5830,1968 R59.1@5830,1937.56
NetLD10_1: LD10.1 R69.2 | length 55
  Bottom Layer w10: R69.2@5334,953.56 5335.46,955.02 LD10.1@5335.46,1008
NetLD12_1: LD12.1 R150.1 | length 69.9
  Bottom Layer w5: R150.1@1015,1942.3 1044.94,1942.27 1056.75,1930.47 LD12.1@1080,1930.49
NetLD12_2: LD12.2 Q3.3 | length 99
  Bottom Layer w5: LD12.2@1080,1989.54 1109.53,1960 1160,1960 Q3.3@1166.7,1960
NetQ3_1: Q3.1 R130.2 SB56.2 | length 261.8
  Bottom Layer w5: Q3.1@1253.33,1997.42 1300.32,1997.4 R130.2@1320,1977.73 1384.6,1977.72 SB56.2@1471.1,1891.22
NetQ4_1: Q4.1 Q4.3 U26.8 | length 142.3
  Bottom Layer w10: 812.76,2490.91 819.14,2484.52 U26.8@819.15,2445.51
  Bottom Layer w20: 1095,2681.34 Q4.1@1095,2713.98 1115.82,2713.98
  Bottom Layer w25: 995,2673.15 Q4.3@995,2713.98
NetQ5_1: Q5.1 Q5.3 U26.6 | length 138.9
  Bottom Layer w10: 761.88,2441.78 776.04,2441.78 U26.6@779.77,2445.51 779.77,2453.9 767.76,2465.91
  Bottom Layer w20: 795,2681.67 Q5.1@795,2714.3 815.82,2714.3
  Bottom Layer w25: 695,2673.67 Q5.3@695,2714.3
NetQ7_1: Q7.1 R158.2 R161.1 | length 165
  Bottom Layer w20: Q7.1@593.32,1937.41 671.82,1937.41 677.47,1931.75 677.47,1856.84 R158.2@674.93,1854.3
NetQ8_1: Q8.1 R162.1 R163.2 | length 173.2
  Top Layer w20: R163.2@512.76,2223.35 R162.1@587.76,2223.35 593.32,2217.78 v1(593.32,2185.91)
  Bottom Layer w20: Q8.1@593.32,2127.41 v1(593.32,2185.91)
NetQ9_1: Q9.1 R168.2 R171.2 | length 143
  Bottom Layer w5: R171.2@120,600.61 R168.2@185,600.61 252.77,600.59 Q9.1@260.01,593.35
NetQ9_3: Q9.3 R5.1 | length 141.7
  Top Layer w5: R5.1@318.21,650 380,650 v1(399.25,630.75)
  Bottom Layer w5: Q9.3@346.64,630.75 357.99,630.75 v1(399.25,630.75)
NetQ10_1: Q10.1 R169.2 R170.2 | length 137.1
  Bottom Layer w5: R170.2@125,733.16 131.99,733.16 182.44,733.15 R169.2@185,730.61 187.44,728.15 252,728.15 Q10.1@260.01,728.16
NetQ10_3: Q10.3 R6.1 | length 90
  Top Layer w5: R6.1@318.21,730 355,730 v1(360,725)
  Bottom Layer w5: Q10.3@346.63,765.56 346.63,738.36 v1(360,725)
NetR1_1: R1.1 SW1.1 | length 98.8
  Top Layer w5: R1.1@210.19,1204.68 210.16,1119.84 SW1.1@220,1110
NetR2_1: R2.1 U1.4 | length 48.9
  Bottom Layer w5: U1.4@394.98,3051.43 437.24,3051.42 R2.1@441.93,3056.11
NetR8_2: R8.2 U1.2 | length 54
  Bottom Layer w5: R8.2@275,3051.42 U1.2@329,3051.43
NetR46_2: R46.2 R104.1 U18.7 | length 135.9
  Top Layer w5: v1(4442.56,1710) R46.2@4442.56,1738.4
  Bottom Layer w5: R104.1@4442.56,1738.4 v1(4442.56,1710) 4471.54,1681.01 U18.7@4471.56,1642.89
NetR47_2: R47.2 R102.1 U18.8 | length 126.8
  Top Layer w5: v1(4487.56,1708.66) R47.2@4487.56,1738.4
  Bottom Layer w5: R102.1@4487.56,1738.4 v1(4487.56,1708.66) 4491.22,1705 U18.8@4491.25,1642.89
NetR48_1: R48.1 R96.2 U18.11 | length 143.6
  Top Layer w5: v1(4585.75,1705) R48.1@4585.75,1738.4
  Bottom Layer w5: U18.11@4550.28,1647 4550.28,1665.28 4585.75,1700.75 v1(4585.75,1705) R96.2@4585.75,1738.4 ; U18.11@4550.3,1642.89 U18.11@4550.29,1646.99
NetR50_1: R50.1 U14.D4 | length 41.8
  Top Layer w4: R50.1@4775,2142.29 4775,2121.49 v2(4777.04,2119.44)
  Bottom Layer w4: U14.D4@4764.27,2106.67 v2(4777.04,2119.44)
NetR55_1: R55.1 U14.P3 | length 152.2
  Bottom Layer w5: R55.1@4647.76,2473.19 4654.48,2473.18 4727.26,2400.41 4727.26,2374 U14.P3@4738.68,2362.58
NetR76_1: R76.1 R77.1 R80.1 U13.7 | length 147
  Bottom Layer w10: R80.1@5140,1897.72 R77.1@5185,1897.72 R76.1@5230,1897.72 5238.2,1905.92 U13.7@5238.2,1951.23
NetR78_1: R78.1 U14.F15 | length 100.1
  Bottom Layer w5: U14.F15@5045.77,2157.85 5143.53,2157.84 R78.1@5145.18,2156.22
NetR79_1: R79.1 U14.J15 | length 108.4
  Bottom Layer w5: U14.J15@5045.77,2234.63 5057.61,2234.6 5073,2250 5138.94,2250 R79.1@5145.18,2256.22
NetR83_1: R83.1 R84.2 U16.4 | length 205.5
  Bottom Layer w20: 4777.29,1437.57 R83.1@4805,1437.56 ; 4777.29,1497.44 R84.2@4805,1497.45 ; 4805,1458.18 R83.1@4805,1437.56 ; 4805,1476.83 R84.2@4805,1497.45 ; 4832.71,1437.57 R83.1@4805,1437.56 ; 4832.71,1497.44 R84.2@4805,1497.45 ; 4858.09,1492.59 U16.4@4891.7,1492.6 4891.7,1472.76
NetR89_2: R89.2 R90.1 U18.14 | length 119.9
  Bottom Layer w12: U18.14@4597.55,1595.64 4652.57,1595.62 R89.2@4663.06,1606.09
  Bottom Layer w20: R89.2@4663.06,1606.09 R90.1@4663.06,1656.09
NetR97_1: R97.1 R101.2 U17.5 | length 104.5
  Bottom Layer w15: R101.2@4498.6,2794.77 4500.87,2792.5 4536.17,2792.5 R97.1@4546.02,2802.35 4572.65,2802.34 4580.21,2794.78 U17.5@4594.86,2794.8
NetR105_1: R105.1 U18.24 | length 114.2
  Bottom Layer w5: R105.1@4405,1402.73 4471.55,1469.28 U18.24@4471.56,1489.34
NetR110_2: R110.2 X3.1 | length 57.2
  Bottom Layer w5: X3.1@3298.7,1039.75 3323.59,1039.75 3325.63,1037.72 R110.2@3355,1037.72
NetR114_1: R114.1 X3.3 | length 49.5
  Bottom Layer w5: R114.1@3198.61,1080.51 3221.13,1080.51 3222.53,1079.11 X3.3@3247.52,1079.12
NetR116_1: R116.1 TP9.1 U23.A5 | length 165.2
  Bottom Layer w5: U23.A5@2451.26,319.44 2515.82,319.44 2537.08,298.19 2537.08,263.62 TP9.1@2562.52,238.19
NetR127_1: R127.1 U24.3 | length 106.3
  Bottom Layer w5: U24.3@1017.91,1174.41 1036.41,1174.41 1090,1228 R127.1@1090,1240
NetR129_1: R129.1 U24.2 | length 150.3
  Bottom Layer w5: U24.2@1017.91,1190.16 1033.16,1190.16 1060,1217 1060,1280 1070,1290 R129.1@1090,1290
NetR131_1: R131.1 U24.1 | length 180.3
  Bottom Layer w5: U24.1@1020.87,1205.91 1025.91,1205.91 1045,1225 1045,1320 1065,1340 R131.1@1090,1340
NetR147_1: R147.1 R151.2 U26.11 | length 142.5
  Bottom Layer w10: U26.11@894.93,2409.1 904.1,2409.09 934.17,2439.17 952,2439.17 R151.2@975,2439.19 R147.1@1025,2439.19
NetR152_1: R152.1 U26.16 | length 83.3
  Bottom Layer w5: U26.16@858.5,2293.92 858.5,2282.49 884,2256.99 884,2242.56 R152.1@899.12,2227.44
NetR153_2: R153.2 U26.17 | length 72.9
  Bottom Layer w5: U26.17@838.83,2293.94 838.81,2242.75 R153.2@854.12,2227.44
NetR155_2: R155.2 U26.18 | length 72.7
  Bottom Layer w5: R155.2@804.12,2227.44 819.12,2242.43 819.12,2270 U26.18@819.15,2293.94
NetR156_1: R156.1 R159.1 U27.6 | length 129.6
  Bottom Layer w5: R159.1@720,1458.95 R156.1@785,1458.95 785,1486 805.32,1506.32 U27.6@805.34,1515.13
NetR172_2: R172.2 U33.15 | length 207.5
  Top Layer w20: v1(4357.76,577.24) 4357.76,630.84 4371.91,645 R172.2@4457.29,645
  Bottom Layer w20: v1(4357.76,577.24) U33.15@4357.76,625.78
NetR175_2: R175.2 U33.10 | length 84
  Top Layer w20: v1(4607.76,575) 4607.76,605.03 R175.2@4610,607.28
  Bottom Layer w20: v1(4607.76,575) U33.10@4607.76,625.78
NetSB30_2: SB30.2 U22.C1 | length 543.8
  Bottom Layer w10: U22.C1@2913.89,1511.24 2948,1545.35 2948,1602 2925,1625 2925,1732.48 2967.52,1775 3032.01,1775 3092.01,1715 SB30.2@3181.38,1715
NetSB32_2: SB32.2 SB33.2 U22.G7 U22.G9 U22.J7 U22.J9 | length 86.2
  Bottom Layer w10: v2(2646.15,1306.5) U22.J9@2661.91,1322.25 ; v2(2649.22,1372.57) U22.G9@2661.92,1385.25 ; U22.J7@2724.9,1322.25 2736.15,1311 v2(2742,1311) ; U22.G7@2724.9,1385.25 2724.9,1388.4 v2(2739.75,1403.25)
  other v1: 2950,1825 2950,1850
NetSB36_2: SB36.2 SB44.2 U22.G1 | length 264
  Bottom Layer w10: U22.G1@2913.89,1385.25 2933.76,1405.14 2934.5,1405.14 2944.32,1415 2955.01,1415
  Bottom Layer w15: 2955.01,1415 2970.68,1430.67 SB36.2@3100,1430.66 3111.38,1442.05 SB44.2@3111.38,1485
NetSB37_2: SB37.2 SB39.2 U22.G2 | length 228.9
  Top Layer w15: v2(2898.11,1400.98) 2940,1400.98 2987.64,1448.61 SB37.2@3085,1448.62
  Bottom Layer w10: U22.G2@2882.39,1385.25 v2(2898.11,1400.98)
NetSB62_1: SB62.1 U27.12 | length 94
  Bottom Layer w5: U27.12@844.69,1627.34 844.69,1692.61 SB62.1@865,1712.93
NetSB63_1: SB63.1 U27.10 | length 86.4
  Bottom Layer w5: SB63.1@800,1711.55 805.32,1706.23 U27.10@805.34,1627.34
NetSB65_2: SB65.2 U26.4 | length 102.6
  Bottom Layer w10: SB65.2@642.76,2384.53 647.63,2389.4 U26.4@743.36,2389.41
NetTP6_1: TP6.1 U17.3 | length 103.4
  Bottom Layer w20: U17.3@4697.23,2757.39 4733.62,2757.38 TP6.1@4781,2710
NetTP10_1: TP10.1 U23.C5 | length 111.3
  Bottom Layer w4: U23.C5@2451.26,398.19 2495,398.19
  Bottom Layer w5: 2495,398.19 TP10.1@2562.52,398.19
NRST: B1.3 B1.4 C75.2 CN2.36 CN5.10 CN8.10 CN12.3 D1.2 R55.2 U6.1 U11.3 U18.15 U22.J4 | length 11656.7
  Top Layer w5: CN2.36@2702.88,2646.31 v1(2702.87,2705) ; v2(2836.91,1304.43) 2844.04,1304.43 2860.6,1321 2874,1321 2890,1305 2902.01,1305 2927.01,1280 2955,1280 2975,1260 2975,1240 3003,1212 3080.28,1212 C75.2@3096.28,1196 3121.28,1171 3142,1171 3173,1202 3460.78,1202 3522.5,1263.72 3522.5,1466.52 3650,1594.02 3650,1655 3729.24,1734.25 v1(3744.26,1734.25) 4114.25,1734.25 4230,1850 4496,1850 4512.5,1833.5 4512.5,1762.5 4537,1738 4537,1693 4575,1655 4575,1626 4629,1572 v1(4629,1569.07) ; v1(5272.76,2858.5) 5243.5,2858.5 5181,2796 5181,2571 5150,2540 5150,2270 5210,2210 5286.01,2210 5505,1991 5505,1770 v1(5567.5,1707.5) 5567.5,1610.01 CN5.10@5676.3,1501.22 5540.01,1364.92 5540.01,1284.01 5534.35,1278.35 5534.35,1233.39 5547.74,1220 5642.03,1220 B1.3@5642.52,1220.49 B1.4@5642.52,1000.02
  L3_SIG w4: v1(2530,189.99) 2545,189.99 2553,181.99 3482,181.99 3675,374.99 3675,1610 3744.26,1679.25 v1(3744.26,1734.25) 3744.26,1805.75 3620,1930 3620,2590 3535,2675 3095,2675 3045,2725 2722.87,2725 v1(2702.87,2705) ; v1(4615.48,2508.62) 4666.85,2560 5010,2560 5240,2790 5240,2825.74 v1(5272.76,2858.5)
  Bottom Layer w4: U22.J4@2819.38,1322.25 2836.82,1304.81 2836.82,1304.52 v2(2836.91,1304.43)
  Bottom Layer w5: D1.2@2494.99,163.43 2494.99,174.98 2510.68,190.68 2529.32,190.68 v1(2530,189.99) ; CN12.3@3674,1734.25 v1(3744.26,1734.25) ; U18.15@4597.54,1575.94 4609.99,1575.94 v1@4622.06,1575.93 ; v1(4615.48,2508.62) R55.2@4647.76,2508.62 ; v1(4629,1569.07) 4653.07,1545 4690,1545 4845,1700 5175,1700 5225,1750 5525,1750 v1(5567.5,1707.5) ; CN8.10@5190.13,2891 5287.85,2891 5289.29,2892.43 U11.3@5297.17,2892.44 5297.17,2880.32 5275.35,2858.5 v1(5272.76,2858.5)
OCTOSPI_CLK: TP34.1 U22.J14 U23.B2 | length 1425.2
  Top Layer w5: v2(2313.47,339.14) 2298,354.61 2298,384.98 2303.01,389.99 2369.66,389.99 2374.66,394.99 2374.66,516.56 2215,676.22 2215,743.59 2220,748.59 2244,748.59 2250,754.59 2250,763.59 2245,768.59 2220,768.59 2215,773.59 2215,783.59 2220,788.59 2245,788.59 2250,793.59 2250,1167.56 2275,1192.56 2275,1192.72 2283.19,1200.91 TP34.1@2312.76,1200.91 2325.91,1200.91 2350.91,1225.91 2409.69,1225.91 2427,1243.22 2427,1268.82 2450.18,1292 2483.01,1292 2488.67,1297.66 v2(2488.67,1306.5)
  Bottom Layer w5: v2(2488.67,1306.5) U22.J14@2504.43,1322.25
  Bottom Layer w5.22: v2(2313.47,339.14) U23.B2@2333.15,358.81
OCTOSPI_DQS: TP33.1 U22.G14 U23.C3 | length 1425.1
  Top Layer w5: v2(2352.84,417.86) 2335,435.7 2335,460 2320,475 2309.99,475 2292,492.99 2292,503 2126.09,668.91 2126.09,963.09 2130,967 2149,967 2155,973 2155,1139.5 2150,1144.5 2138,1144.5 2133,1149.5 2133,1159.5 2138,1164.5 2150,1164.5 2155,1169.5 2155,1220 2265,1330 2337.76,1330 2342.76,1335 2342.76,1350.48 2348.19,1355.91 TP33.1@2372.76,1355.91 2395.91,1355.91 2425.98,1385.98 2462.69,1385.98 2477.69,1400.98 v2(2488.67,1400.98)
  Bottom Layer w5: v2(2352.84,417.86) U23.C3@2372.52,398.19 ; v2(2488.67,1400.98) U22.G14@2504.4,1385.25
OCTOSPI_IO0: TP35.1 U22.H15 U23.D3 | length 1429.9
  Top Layer w5: v2(2352.84,457.24) 2352.84,467.16 2335,485 2335,510 2185,660 2185,682.75 2180,687.75 2168,687.75 2163,692.75 2163,702.75 2168,707.75 2180,707.75 2185,712.75 2185,722.75 2180,727.75 2161.09,727.75 2156.09,732.75 2156.09,742.75 2161.09,747.75 2180,747.75 2185,752.75 2185,762.75 2180,767.75 2161.09,767.75 2156.09,772.75 2156.09,782.75 2161.09,787.75 2180,787.75 2185,792.75 2185,1025 2190,1030 2215,1030 2220,1035 2220,1075.27 2215,1080.27 2190,1080.27 2185,1085.27 2185,1095.27 2190,1100.27 2215,1100.27 2220,1105.27 2220,1115.27 2215,1120.27 2190,1120.27 2185,1125.27 2185,1135.27 2190,1140.27 2215,1140.27 2220,1145.27 2220,1205 2265.91,1250.91 TP35.1@2312.76,1250.91 2318.63,1250.91 2352.72,1285 2390,1285 v2(2405,1300)
  Bottom Layer w5: v2(2352.84,457.24) U23.D3@2372.52,437.56 ; v2(2405,1300) 2458.74,1353.74 U22.H15@2472.94,1353.76
OCTOSPI_IO1: TP36.1 U22.G13 U23.D2 | length 1433
  Top Layer w5: v2(2313.47,457.24) 2297.76,457.24 2275,480 2266,480 2096.09,649.91 2096.09,1226.09 2210.26,1340.25 2248.94,1378.92 2249.15,1378.72 2310.87,1378.72 2311.08,1378.92 2313.94,1378.92 2350.9,1415.91 ; TP36.1@2377.76,1415.91 2378.33,1416.48 2504.67,1416.48 v2(2520.17,1400.98)
  Top Layer w5.22: 2350.9,1415.91 TP36.1@2377.76,1415.91
  Bottom Layer w5: v2(2520.17,1400.98) U22.G13@2535.9,1385.25
  Bottom Layer w5.22: v2(2313.47,457.24) U23.D2@2333.15,437.56
OCTOSPI_IO2: TP37.1 U22.K14 U23.C4 | length 1429.5
  Top Layer w5: v2(2431.57,417.86) 2450,436.3 2450,470 2445,475 2425,475 2415,485 2415,545 2410,550 2390,550 2385,555 2385,565 2390,570 2410,570 2415,575 2415,585 2394.44,605.56 2394.44,612.64 2409.24,627.43 2409.24,634.51 2402.17,641.59 2395.09,641.59 2380.29,626.78 2373.21,626.78 2366.14,633.85 2366.14,640.93 2380.94,655.74 2380.94,662.82 2373.87,669.89 2366.79,669.89 2351.99,655.09 2344.91,655.09 2337.84,662.16 2337.84,669.24 2352.64,684.03 2352.64,691.11 2345.57,698.18 2338.49,698.18 2323.69,683.39 2316.61,683.39 2309.54,690.45 2309.54,697.53 2324.34,712.34 2324.34,719.42 2317.27,726.49 2310.19,726.49 2295.39,711.68 2288.31,711.68 2280,720 2280,1090.75 2285,1095.75 2294,1095.75 2299,1100.75 2299,1110.75 2294,1115.75 2285,1115.75 2280,1120.75 2280,1132.72 2293.19,1145.91 TP37.1@2312.76,1145.91 2313.67,1145 2327.72,1145 2353.73,1171 2392.68,1171 2397.18,1166.5 2418.34,1166.5 2435,1183.16 2435,1210.34 2449.66,1225 2449.66,1244.66 2480.01,1275 v2(2488.67,1275)
  Bottom Layer w5: U23.C4@2411.89,398.19 v2(2431.57,417.86) ; v2(2488.67,1275) U22.K14@2504.44,1290.76
OCTOSPI_IO3: TP38.1 U22.K15 U23.D4 | length 1422.8
  Top Layer w5: v2(2431.57,457.24) 2431.57,450.56 2424.01,442.99 2402,442.99 2395,449.99 2395,517.43 2349.92,562.51 2349.92,569.59 2371.62,591.3 2371.62,598.38 2364.55,605.44 2357.47,605.44 2335.77,583.75 2328.69,583.75 2321.62,590.82 2321.62,597.9 2343.32,619.59 2343.32,626.67 2336.25,633.75 2329.17,633.75 2307.47,612.05 2300.39,612.05 2293.32,619.11 2293.32,626.19 2315.02,647.9 2315.02,654.98 2307.95,662.05 2300.87,662.05 2279.17,640.34 2272.09,640.34 2265,647.43 2265,665.61 2260,670.61 2245,670.61 2240,675.61 2240,685.61 2245,690.61 2260,690.61 2265,695.61 2265,705.61 2260,710.61 2235,710.61 2230,715.61 2230,725.61 2235,730.61 2260,730.61 2265,735.61 2265,1161.34 2279.57,1175.91 2327.75,1175.91 2352.75,1200.91 TP38.1@2367.76,1200.91 2376.85,1210 2415,1210 2440,1235 2440,1257.83 v2(2457.18,1275)
  Bottom Layer w5: U23.D4@2411.89,437.56 v2(2431.57,457.24) ; v2(2457.18,1275) U22.K15@2472.94,1290.76
OCTOSPI_IO4: TP39.1 U22.K13 U23.D5 | length 1421.8
  Top Layer w5: v2(2470.94,457.24) 2503,489.3 2503,546 2476.9,572.09 2469.82,572.09 2454.4,556.67 2447.32,556.67 2440.75,563.25 2440.75,572.33 2463.17,594.75 2463.17,601.83 2456.1,608.9 2449.02,608.9 2438.6,598.48 2431.52,598.48 2424.45,605.55 2424.45,612.62 2434.87,623.05 2434.87,630.12 2359.91,705.09 2359.91,712.17 2368.83,721.09 2368.83,728.17 2361.76,735.24 2354.68,735.24 2345.76,726.32 2338.68,726.32 2331.58,733.42 2331.58,740.5 2342,750.92 2342,758 2334.93,765.07 2327.85,765.07 2317.43,754.65 2310.35,754.65 2295,770 2295,813.38 2300,818.38 2320,818.38 2325,823.38 2325,833.38 2320,838.38 2300,838.38 2295,843.38 2295,853.38 2300,858.38 2320,858.38 2325,863.38 2325,873.38 2320,878.38 2300,878.38 2295,883.38 2295,893.38 2300,898.38 2320,898.38 2325,903.38 2325,913.38 2320,918.38 2300,918.38 2295,923.38 2295,1068.15 TP39.1@2367.76,1140.91 2371.85,1145 2428,1145 2445.6,1162.59 2462.6,1162.59 2471.68,1171.67 2471.68,1237.5 2509.59,1275.42 2519.8,1275.35 v2(2520.17,1275)
  Bottom Layer w5: U23.D5@2451.26,437.56 v2(2470.94,457.24) ; v2(2520.17,1275) U22.K13@2535.94,1290.76
OCTOSPI_IO5: TP40.1 U22.H14 U23.E3 | length 1427.7
  Top Layer w5: v2(2352.84,496.6) 2352.84,517.16 2200,670 2200,804.88 2205,809.88 2216,809.88 2221,814.88 2221,824.88 2216,829.88 2205,829.88 2200,834.88 2200,845 2205,850 2230,850 2235,855 2235,865 2230,870 2205,870 2200,875 2200,885 2205,890 2230,890 2235,895 2235,905 2230,910 2205,910 2200,915 2200,925 2205,930 2230,930 2235,935 2235,945 2230,950 2205,950 2200,955 2200,965 2205,970 2230,970 2235,975 2235,985 2230,990 2205,990 2200,995 2200,1005 2205,1010 2230,1010 2235,1015 2235,1195 2265.91,1225.91 2329.69,1225.91 2354.69,1250.91 TP40.1@2372.76,1250.91 2398.63,1250.91 2407.72,1260 2407.72,1277.72 v2(2430,1300)
  Bottom Layer w5: v2(2352.84,496.6) U23.E3@2372.52,476.93 ; v2(2430,1300) 2467,1337 2487.67,1337 U22.H14@2504.44,1353.76
OCTOSPI_IO6: TP41.1 U22.H13 U23.E2 | length 1433.9
  Top Layer w5: v2(2313.47,496.6) 2313.47,506.52 2141.09,678.91 2141.09,805.24 2146.09,810.24 2165,810.24 2170,815.24 2170,825.24 2165,830.24 2146.09,830.24 2141.09,835.24 2141.09,845.24 2146.09,850.24 2165,850.24 2170,855.24 2170,865.24 2165,870.24 2146.09,870.24 2141.09,875.24 2141.09,885.24 2146.09,890.24 2165,890.24 2170,895.24 2170,910.73 2165,915.73 2157,915.73 2152,920.73 2152,930.73 2157,935.73 2165,935.73 2170,940.73 2170,1182.72 2288.19,1300.91 TP41.1@2312.76,1300.91 2350.91,1300.91 v1(2355,1305)
  Bottom Layer w5: v2(2313.47,496.6) U23.E2@2333.15,476.93 ; v1(2355,1305) 2355,1370 2380,1395 2440,1395 2465,1370 2519.65,1370 U22.H13@2535.9,1353.75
